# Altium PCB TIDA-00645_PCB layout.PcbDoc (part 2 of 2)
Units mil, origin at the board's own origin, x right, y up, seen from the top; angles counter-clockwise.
Board outline 3000 x 2000 mil, 2 copper layers (Top Layer, Bottom Layer), stack 62 mil thick; 97 components, 65 nets, 273 pads, 637 vias.
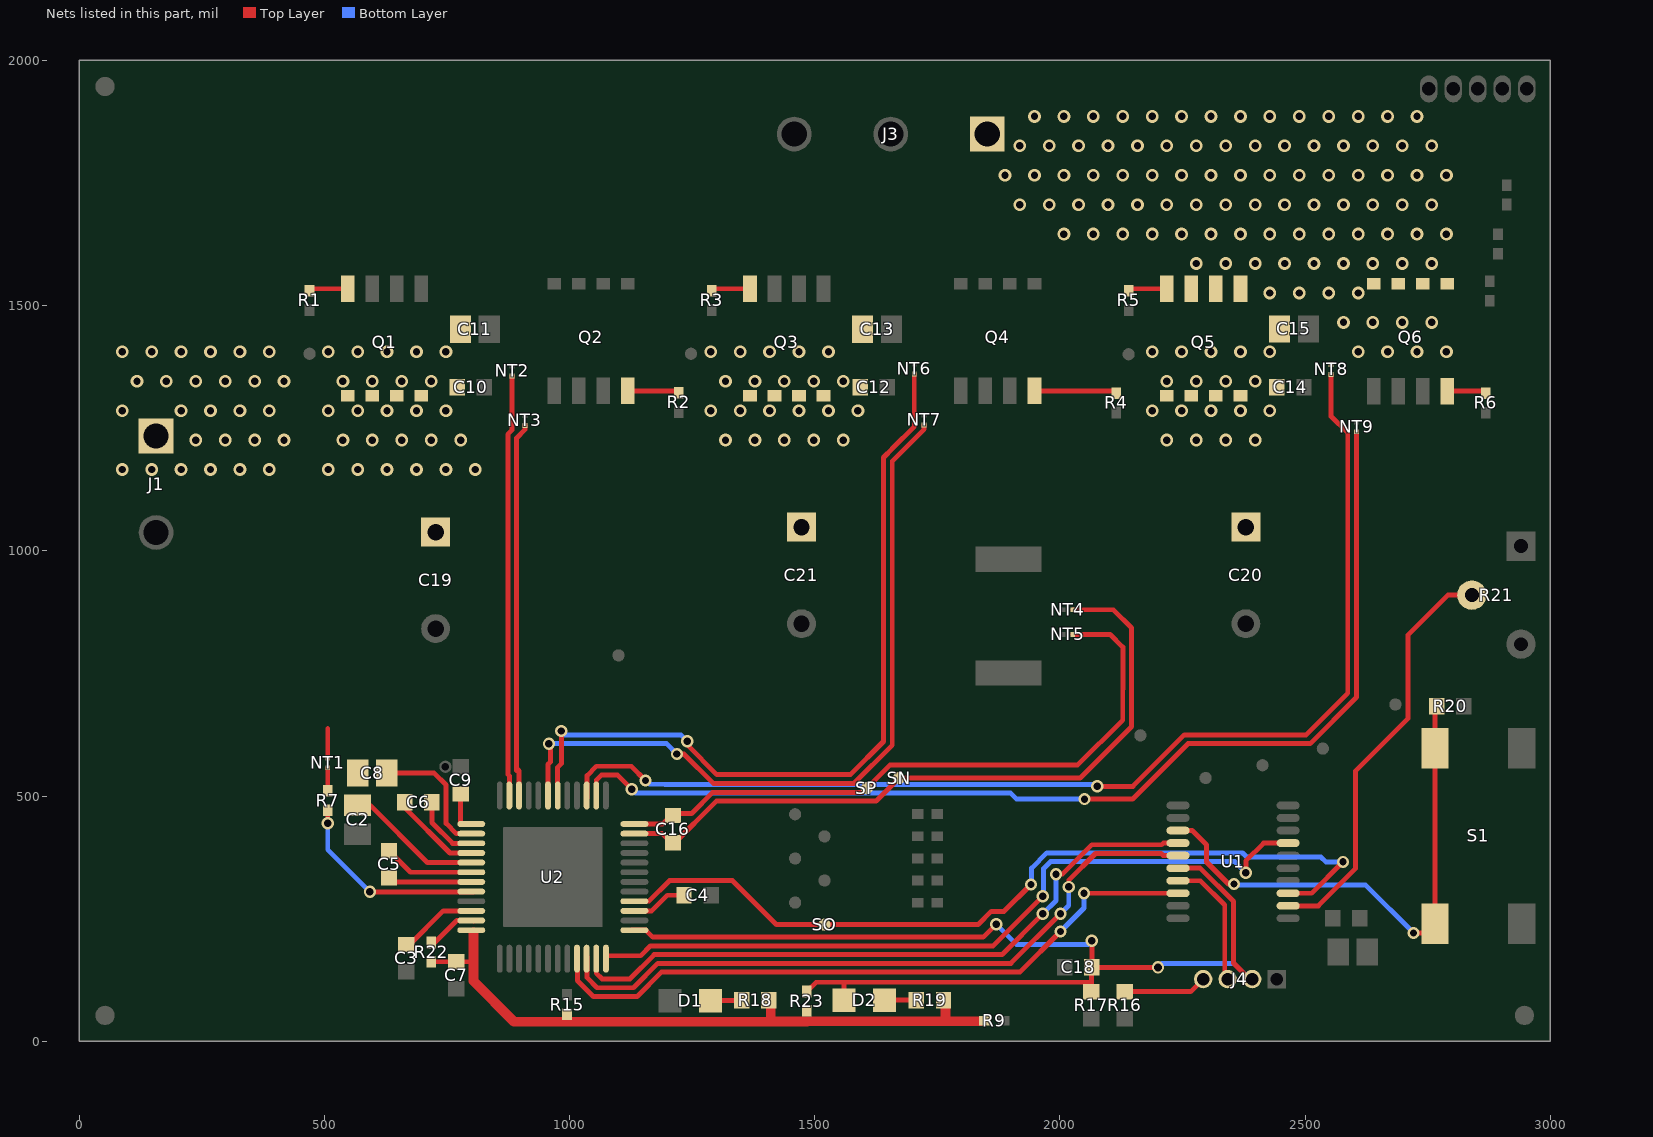
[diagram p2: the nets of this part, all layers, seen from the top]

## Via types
v1: diameter 26, hole 15, Top Layer to Bottom Layer, tented both sides, 555 vias
v2: diameter 25, hole 15, Top Layer to Bottom Layer, 56 vias
v3: diameter 19.68, hole 7.87, Top Layer to Bottom Layer, 25 vias
v4: diameter 25, hole 16, Top Layer to Bottom Layer, 1 vias

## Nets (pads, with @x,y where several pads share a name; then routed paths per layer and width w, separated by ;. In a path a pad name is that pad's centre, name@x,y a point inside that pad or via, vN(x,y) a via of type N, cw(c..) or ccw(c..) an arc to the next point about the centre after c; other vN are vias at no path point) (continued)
M_C: J3.1 NT8.2 Q5.1 Q5.2 Q5.3 Q6.5 Q6.6 Q6.7 Q6.8
  other v1: 2608,1406 2668,1406 2728,1406 2788,1406 2578,1466 2638,1466 2698,1466 2758,1466 2428,1526 2488,1526 2548,1526 2608,1526 2278,1586 2338,1586 2398,1586 2458,1586 2518,1586 2578,1586 2638,1586 2698,1586 2758,1586 2008,1646 2068,1646 2128,1646 2188,1646 2248,1646 2308,1646 2368,1646 2428,1646 2488,1646 2548,1646 2608,1646 2668,1646 2728,1646 2788,1646 1918,1706 1978,1706 2038,1706 2098,1706 2158,1706 2218,1706 2278,1706 2338,1706 2398,1706 2458,1706 2518,1706 2578,1706 2638,1706 2698,1706 2758,1706 1888,1766 1948,1766 2008,1766 2068,1766 2128,1766 2188,1766 2248,1766 2308,1766 2368,1766 2428,1766 2488,1766 2548,1766 2608,1766 2668,1766 2728,1766 2788,1766 1918,1826 1978,1826 2038,1826 2098,1826 2158,1826 2218,1826 2278,1826 2338,1826 2398,1826 2458,1826 2518,1826 2578,1826 2638,1826 2698,1826 2758,1826 1948,1886 2008,1886 2068,1886 2128,1886 2188,1886 2248,1886 2308,1886 2368,1886 2428,1886 2488,1886 2548,1886 2608,1886 2668,1886 2728,1886
NetC3_1: C3.1 U2.46 | length 167
  Top Layer w10: C3.1@667,197.56 674.01,197.56 742.56,266.1 U2.46@805.57,266.1
NetC4_1: C4.1 U2.15 | length 120.2
  Top Layer w10: U2.15@1126.43,266.1 1167.44,266.1 1199.34,298 C4.1@1233.44,298
NetC5_1: C5.1 U2.42 | length 191.7
  Top Layer w10: C5.1@632,388.56 675.72,344.84 U2.42@805.57,344.84
NetC5_2: C5.2 U2.43 | length 177
  Top Layer w10: C5.2@632,333.44 640.28,325.16 U2.43@805.57,325.16
NetC6_1: C6.1 U2.40 | length 191.1
  Top Layer w10: C6.1@664.44,488 664.44,476 756.23,384.21 U2.40@805.57,384.21
NetC6_2: C6.2 U2.39 | length 145.4
  Top Layer w10: C6.2@719.56,488 719.56,446.16 761.82,403.9 U2.39@805.57,403.9
NetC8_2: C8.2 U2.38 | length 274.9
  Top Layer w10: C8.2@627.53,547 724.12,547 748.39,522.72 748.39,444.61 769.42,423.58 U2.38@805.57,423.58
NetC9_2: C9.2 U2.37 | length 88.7
  Top Layer w10: C9.2@778,504.44 778,443.27 U2.37@805.57,443.27
NetD1_1: D1.1 R18.1 | length 59.2
  Top Layer w10: D1.1@1287.34,83 R18.1@1346.5,83
NetD2_1: D2.1 R19.1 | length 61.2
  Top Layer w10: D2.1@1642.34,84 R19.1@1703.5,84
NetJ4_4: J4.4 R16.1 | length 170.5
  Top Layer w10: R16.1@2132,101.56 2266.56,101.56 J4.4@2292,127
NetQ1_4: Q1.4 R1.2 | length 77.8
  Top Layer w10: R1.2@470,1534.62 Q1.4@547.76,1534.62
NetQ2_4: Q2.4 R2.2 | length 103.6
  Top Layer w10: Q2.4@1118.91,1326.17 R2.2@1222.55,1326.17
NetQ3_4: Q3.4 R3.2 | length 77.8
  Top Layer w10: R3.2@1290,1534.62 Q3.4@1367.76,1534.62
NetQ4_4: Q4.4 R4.2 | length 166.5
  Top Layer w10: Q4.4@1947.91,1326.17 R4.2@2114.45,1326.17
NetQ5_4: Q5.4 R5.2 | length 77.8
  Top Layer w10: R5.2@2140,1534.62 Q5.4@2217.76,1534.62
NetQ6_4: Q6.4 R6.2 | length 77.5
  Top Layer w10: Q6.4@2789.91,1326 R6.2@2867.45,1326
NetR7_1: R7.1 U2.44 | length 415.2
  Top Layer w10: v2(507,445) R7.1@507,471.32 ; v2(593,305) 593.18,304.82 654.06,304.82 654.25,305 804.23,305 804.66,304.57 U2.44@805.57,305.47
  Bottom Layer w10: v2(507,445) 507,391 v2(593,305)
POT: R21.2 U1.2 | length 853.6
  Top Layer w10: U1.2@2465.2,276.43 2526.85,276.43 2602.37,351.95 2602.37,551.1 2710,658.72 2710,829 2791,910 R21.2@2840,910
PUSH: R20.1 S1.1 S1.2 U1.13 | length 1081.6
  Top Layer w10: U1.13@2240.8,429.98 2269.73,429.98 2298.71,400.99 2298.71,365.84 2343.56,321 v2(2355,321) ; v2(2721,221) 2745.55,221 S1.1@2764.42,239.87 S1.2@2764.42,598.13 R20.1@2764.42,682.91
  Bottom Layer w10: v2(2355,321) 2357.37,318.63 2623.37,318.63 v2(2721,221)
PVDD: C2.1 C8.1 C10.1 C11.1 C12.1 C13.1 C14.1 C15.1 C19.1 C20.1 C21.1 J1.1 NT1.2 Q1.5 Q1.6 Q1.7 Q1.8 Q3.5 Q3.6 Q3.7 Q3.8 Q5.5 Q5.6 Q5.7 Q5.8 U2.41 | length 346
  Top Layer w10: NT1.2@507,578 507,638 ; C2.1@568,481.53 593.47,481.53 710.47,364.53 U2.41@805.57,364.53
  other v1: 88,1166 148,1166 208,1166 268,1166 328,1166 388,1166 508,1166 568,1166 628,1166 688,1166 748,1166 808,1166 238,1226 298,1226 358,1226 418,1226 538,1226 598,1226 658,1226 718,1226 778,1226 1318,1226 1378,1226 1438,1226 1498,1226 1558,1226 2218,1226 2278,1226 2338,1226 2398,1226 88,1286 208,1286 268,1286 328,1286 388,1286 508,1286 568,1286 628,1286 688,1286 748,1286 1288,1286 1348,1286 1408,1286 1468,1286 1528,1286 1588,1286 2188,1286 2248,1286 2308,1286 2368,1286 2428,1286 118,1346 178,1346 238,1346 298,1346 358,1346 418,1346 538,1346 598,1346 658,1346 718,1346 1318,1346 1378,1346 1438,1346 1498,1346 1558,1346 2218,1346 2278,1346 2338,1346 2398,1346 88,1406 148,1406 208,1406 268,1406 328,1406 388,1406 508,1406 568,1406 628,1406 688,1406 748,1406 1288,1406 1348,1406 1408,1406 1468,1406 1528,1406 2188,1406 2248,1406 2308,1406 2368,1406 2428,1406
RESET: C18.1 D2.2 J4.2 R17.1 R23.1 U1.16 U2.13 | length 2355
  Top Layer w10: U2.13@1126.43,226.73 1155.73,226.73 1169.84,212.63 1843.63,212.63 v2(1870,239) ; R23.1@1484,101.68 1502.81,120.5 2064.06,120.5 ; D2.2@1559.66,84 1559.66,120.16 ; R17.1@2064,101.56 2064.56,102.12 C18.1@2064.56,151 C18.1@2065,151 ; v2(2065,205) C18.1@2065,151 ; v4(2200,151) C18.1@2065,151 ; U1.16@2240.8,353.2 2286.07,353.2 2353.87,285.4 2353.87,159.78 J4.2@2386.65,127
  Bottom Layer w10: v2(1870,239) 1911.75,197.25 2057.25,197.25 v2(2065,205) ; v4(2200,151) 2207.57,158.57 2355.08,158.57 J4.2@2386.65,127
S_N: C16.1 NT4.1 SN.1 U2.23 | length 1467.8
  Top Layer w10: U2.23@1126.43,423.58 1188.92,423.58 1211,401.5 1299.35,489.85 1624.85,489.85 ; 1624.72,489.72 1624.85,489.85 ; NT4.1@2026,880 2109,880 2146.13,842.87 2146.13,672.13 ; 2146,675 2146,642 2041,537 SN.1@1672,537 1624.85,489.85
S_P: C16.2 NT5.1 SP.1 U2.24 | length 1351.5
  Top Layer w10: U2.24@1126.43,443.27 1189.77,443.27 1211,464.5 1248.71,464.5 1291.95,507.73 1597.73,507.73 SP.1@1606,516 1653.25,563.25 2035.43,563.25 2128,655 2128,718.81 ; NT5.1@2026,830 2102,830 2128.25,803.75 2128.25,718.25
SCLK: U1.7 U2.12 | length 1550.8
  Top Layer w10: U2.12@1074.27,174.57 1145.02,174.57 1165.2,194.75 1863.75,194.75 v2(1965,296) ; v2(2379,344) 2379,368 2415.39,404.39 U1.7@2465.2,404.39
  Bottom Layer w10: v2(1965,296) 1966.37,297.37 1966.37,352.1 1980.65,366.38 2356.62,366.38 v2(2379,344)
SCS: U1.18 U2.9 | length 1393.8
  Top Layer w10: U2.9@1015.21,174.57 1016.12,173.66 1016.12,124.1 1048.72,91.5 1137.78,91.5 1187.41,141.13 1918.13,141.13 v2(2001,224) ; v2(2049,302) U1.18@2240.8,302.02
  Bottom Layer w10: v2(2001,224) 2049,272 v2(2049,302)
SDI: U1.15 U2.10 | length 1404.1
  Top Layer w10: U2.10@1034.9,174.57 1035.8,173.66 1035.8,129.7 1056.13,109.37 1130.37,109.37 1180.01,159 1900,159 v2(2001,260) ; v2(2018,315) 2018,328.72 2072.36,383.09 2206,383.09 2210.29,378.8 U1.15@2240.8,378.8
  Bottom Layer w10: v2(2001,260) 2018,277 v2(2018,315)
SDO: U1.14 U2.11 | length 1373
  Top Layer w10: U2.11@1054.58,174.57 1054.58,139.15 1066.49,127.24 1122.97,127.24 1172.6,176.88 1881.88,176.88 v2(1965,260) ; v2(1992,341) 2005,341 2064.96,400.96 2207.19,400.96 2210.61,404.39 U1.14@2240.8,404.39
  Bottom Layer w10: v2(1965,260) 1992,287 v2(1992,341)
SH_A: NT2.1 U2.35 | length 862
  Top Layer w10: 874.25,544.47 874.25,1238 883,1246.75 NT2.1@883,1357 ; U2.35@877.42,495.43 877.42,541.31
SH_B: NT6.1 U2.30 | length 1646.3
  Top Layer w10: U2.30@975.84,495.43 975.84,558.84 983.37,566.37 983.37,632.63 v2@986,630 ; v2(1240,612) 1240,604.45 1300.4,544.05 1572.77,544.05 1640.13,611.4 1640.13,1190.53 1658.87,1209.28 1658.87,1209.8 1659.39,1209.8 1703,1253.4 NT6.1@1703,1361
  Bottom Layer w10: v2(983,633) 991.13,624.87 1227.13,624.87 v2(1240,612)
SH_C: NT8.1 U2.27 | length 2365.8
  Top Layer w10: U2.27@1034.9,495.43 1035.8,496.34 1035.8,542.01 1054.73,560.94 1126.06,560.94 v2(1155,532) ; v2(2076,520) 2148.72,520 2253.72,625 2502,625 2586.76,709.76 2586.76,1241.24 2553,1274 NT8.1@2553,1360
  Bottom Layer w10: v2(1155,532) 1162.75,524.25 1194.19,524.25 1194.32,524.12 2071.88,524.12 v2(2076,520)
SL_A: NT3.1 U2.34 | length 774.6
  Top Layer w10: 892.13,551.87 892.13,1230.25 909,1247.13 NT3.1@909,1256 ; 892.13,556.87 897.1,551.9 U2.34@897.1,495.43
SL_B: NT7.1 U2.31 | length 1560.8
  Top Layer w10: U2.31@956.16,495.43 956.16,564.74 961.37,569.95 961.37,603.63 v2(958,607) ; v2(1219,586) 1233.18,586 1293,526.18 1580.18,526.18 1658,604 1658,1183.13 1723,1248.13 NT7.1@1723,1257
  Bottom Layer w10: v2(958,607) 1198,607 v2(1219,586)
SL_C: NT9.1 U2.26 | length 2239.2
  Top Layer w10: U2.26@1054.58,495.43 1054.58,532.58 1064.76,542.76 1083,543 1098,543 v2(1127,514) ; v2(2050,494) 2148,494 2261,607 2510,607 2604.63,701.63 2604.63,1196.76 2605,1197.13 NT9.1@2605,1243
  Bottom Layer w10: v2(1127,514) 1134.62,506.38 1186.79,506.38 1186.92,506.25 1899.47,506.25 1911.72,494 v2(2050,494)
SO1: SO.1 U1.3 U2.16 | length 1730.5
  Top Layer w10: U2.16@1126.43,285.79 1161.85,285.79 1204.06,328 1332,328 1422,238 SO.1@1520,238 1833,238 1860,265 1886,265 v2(1941,320) ; U1.3@2465.2,302.02 2513.02,302.02 v2(2577,366)
  Bottom Layer w10: v2(1941,320) 1942.37,321.37 1942.37,353.38 1973.25,384.25 2372.31,384.25 2380.5,376.06 2532.06,376.06 2542.12,366 v2(2577,366)
TEST: J4.3 U1.17 | length 258.8
  Top Layer w10: U1.17@2242.76,327.61 2286.39,327.61 2336,278 J4.3@2336,133
VDRAIN: NT1.1 R7.2 | length 47.3
  Top Layer w10: R7.2@507,510.69 NT1.1@507,558
VREG: C7.1 R9.2 R15.2 R18.2 R19.2 R22.2 R23.2 U2.48 | length 1342.9
  Top Layer w10: R22.2@718,162.31 803.69,162.31
  Top Layer w20: U2.48@804,222.3 804,123 886.97,40.03 995.01,40.14 1410.5,40.56 1484.02,40.64 1766.5,40.92 1842.38,41 R9.2@1843,41 ; 1410.5,42.06 R18.2@1410.5,84 ; 1766.5,41.42 R19.2@1766.5,84
WAKE: R22.1 U2.47 | length 107.4
  Top Layer w10: R22.1@718,201.68 725.42,201.68 770.15,246.42 805.57,246.42 U2.47@804.66,245.51
pads on no net: FID1.1 FID2.1 FID3.1 U2.6 U2.7 U2.17 U2.18

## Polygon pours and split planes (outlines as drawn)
M_C on Top Layer "Top Layer-M_C" (solid, remove dead copper, pour order 45): 1720,2003 1723,2000 2531,2000 2637,2000 2820,1817 2820,1375 2168,1375 1724,1819 1724,1849
M_A on Top Layer "Top Layer-M_A" (solid, remove dead copper, pour order 43): -1,1463.8 -1,1880 118,1999 897,1999 1592,1999 1592,1734 1574,1716 1290,1432 1290,1301 878,1348 878,1463.8 282.03,1331.03
M_B on Top Layer "Top Layer-M_B" (solid, remove dead copper, pour order 41): 1290,1453 1290,1523 1564,1797 1564,1969 1745,1969 1744,1968 1744,1803 1745,1803 1960,1588 2044,1588 2111,1588 2137,1562 2143,1556 2143,1325 1326,1325 1304,1347
BRIDGE on Top Layer "Top Layer-BRIDGE" (solid, remove dead copper, pour order 39): 2598.23,1355 2820,1355 2820,1046 2598.23,824.23 2591.02,835.98 2598.23,977.85
BRIDGE on Top Layer "Top Layer-BRIDGE" (solid, remove dead copper, pour order 38): 1658,876 2163,876 2164,877 2164,934.72 2115,983.72 2118,986.72 2118,1356 1707,1356 1706,1355 1705,1354 1705,1255.4 1640.13,1190.53
BRIDGE on Top Layer "Top Layer-BRIDGE" (solid, remove dead copper, pour order 37): 877,1353 878,1352 1245,1352 1245,930 892,577 874.25,577
PVDD on Top Layer "Top Layer-PVDD" (solid, remove dead copper, pour order 35): 0,1473 786,1473 786,1304 790,1300 791,1301 1247,1301 1247,1444.38 1271.62,1469 1272.62,1470 1609,1470 1609,1301 1610,1300 1650,1300 2142,1300 2144,1302 2144,1468 2458,1468 2458,1300 2466,1300 2568.88,1197.12 2568.88,963.12 2568,964 1246,964 469,964 470,963 470,760 471,760 588,643 588,519 588,463 585,460 541.9,460 541.9,583.1 378,747 378,1110 342,1146 -2,1146
GND on Top Layer "Top Layer-GND" (solid, remove dead copper, pour order 44): -0.43,1780.12 -0.43,-17.5 2997.05,-17.5 3002.05,-12.5 3002.05,1780.12
M_A on Bottom Layer "Bottom Layer-M_A" (solid, remove dead copper, pour order 48): 0,1476.81 0,2000 1567,2000 1570,2003 1580,1993 1580,1686 1580,1683 1230,1333 1224,1327 455.19,1327
M_C on Bottom Layer "Bottom Layer-M_C" (solid, remove dead copper, pour order 47): 1738,2000 1738,1769 1743,1764 2059.03,1447.97 2076.01,1447.97 2366.03,1447.97 2434,1380 2821,1380 2821,1853 2752,1922 2752,1949.87 2752,2002
M_B on Bottom Layer "Bottom Layer-M_B" (solid, remove dead copper, pour order 46): 1361,1450 1361,1593 1361,1594 1564,1797 1564,2000 1744,2000 1744,1803 1745,1803 1960,1588 2111,1588 2153,1546 2153,1452 2121.13,1452 1979.21,1310.08 1946.3,1343 1699,1343
BRIDGE on Bottom Layer "Bottom Layer-BRIDGE" (solid, remove dead copper, pour order 40): 884.65,1295.24 884.65,916.6 2661.6,916.6 2820,1075 2820,1397.96
PVDD on Bottom Layer "Bottom Layer-PVDD" (solid, remove dead copper, pour order 36): 2,1145 874,1145 877.13,1148.13 877.13,1195 2454,1195 2470,1211 2470,1315.3 2470,1434 2471,1435 2471,1458 2471,1460 2455,1476 1363,1476 20,1476 0,1456
GND on Bottom Layer "Bottom Layer-GND" (solid, remove dead copper, pour order 42): -5.28,2000 2994.72,2000 2994.72,-5.57 -5.28,-5.57

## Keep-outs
Keep-Out Layer:
  lines w10: 3000,2000 0,2000 0,0 3000,0 3000,2000 ; 3000,2000 3000,2000
  text ".Layer_Name" at 577,-858.49 h60

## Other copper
Top Layer:
  rectangle net GND: 1066,339 1175,409
  rectangle net PVDD: 594,466 604,474
  rectangle net PVDD: 583,460 609,468
  rectangle net PVDD: 507,583 552,638
  rectangle net BRIDGE: 1723,1297.05 1743,1351
  rectangle net M_A: 878,1372 920,1436
  rectangle net M_B: 1698,1376.39 1738.49,1436
  rectangle net M_C: 2548,1375 2599.39,1426.15
  rectangle net BRIDGE: 1719,1293 1752,1334
  text ".Layer_Name" at 577,-858.49 h60
Bottom Layer:
  text ".Layer_Name" at 577,-858.49 h60

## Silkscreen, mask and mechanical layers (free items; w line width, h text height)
Top Overlay:
  lines w10: 1157,760 1158,761 ; 1158,864 1158,865
  text "TIDA-00645" at 390,1904 h40
  text "MOTA" at 1204,1838 h30
  text "MOTC" at 1993,1838 h30
  text "GND" at 2768,1795 h30 r90
  text "H_C" at 2817,1795 h30 r90
  text "H_B" at 2867,1795 h30 r90
  text "H_A" at 2917,1795 h30 r90
  text "DVCC" at 2969,1765 h30 r90
  text "MOTB" at 1607,1599 h30
  text "PVDD" at 108,1362 h30
  text "SPEED" at 2817,1117 h30
  text "GND" at 120,885 h30
  text "FAULTn" at 1150,140 h30
  text "PWRGD" at 1521,139 h30
  text "DIRECTION" at 2730,138 h30
  text ".Layer_Name" at 577,-858.49 h60
Bottom Overlay:
  text ".Layer_Name" at 577,-858.49 h60
Top Paste:
  text ".Layer_Name" at 577,-858.49 h60
Bottom Paste:
  text ".Layer_Name" at 577,-858.49 h60
Top Solder:
  text ".Layer_Name" at 577,-858.49 h60
  text ".Layer_Name" at 577,-858.49 h60
Bottom Solder:
  text ".Layer_Name" at 577,-858.49 h60
Drill Guide:
  text ".Layer_Name" at 577,-858.49 h60
M1 Board Outline:
  lines w10: 0,0 0,2000 3000,2000 3000,0 ; 0,0 0,0 ; 0,0 3000,0 ; 3000,0 3000,0
  text ".Layer_Name" at 577,-858.49 h60
M2 Board Dimensions:
  rectangle: 125,-400 500,-275
  rectangle: 0,-275 125,-150
  lines w7: 0,-275 1000,-275 ; 125,-400 125,-150 ; 250,-400 250,-150 ; 500,-400 500,-150 ; 750,-400 750,-150 ; 0,-400 0,-150 1000,-150 1000,-400 0,-400
  text ".Layer_Name" at 577,-858.49 h60
M3 3D STEP Top:
  text ".Layer_Name" at 577,-858.49 h60
M4 3D STEP Bottom:
  text ".Layer_Name" at 577,-858.49 h60
M5 Assembly Top:
  lines w10: -292,-930.17 6308,-930.17 ; -292,-726.83 6310,-726.83 ; -292,-523.5 -292,-1133.5 3713,-1133.5 6310,-1133.5 6310,-523.5 -291.5,-523.5 -291.5,-1133.5 1284,-1133.5 ; 2173,-1133.5 2173,-523.5 ; 3440,-726.83 3440,-523.5 ; 4280,-726.83 4280,-523.5 ; 4902,-1140 4902,-937.17
  text "COMPONENTS MARKED 'DNP' SHOULD NOT BE POPULATED." at 1153.5,-318.5 h60
  text "ASSEMBLY VARIANT:" at 1153,-434 h60
  text ".VariantName" at 2189,-434 h60
  text "PCB VIEWED FROM TOP SIDE" at -228.5,-655.67 h60
  text "BOARD #:" at 2248,-655.67 h60
  text ".PRJ_Number" at 2793.5,-655.67 h60
  text "REV:" at 3638,-655.67 h60
  text ".PCB_Rev" at 3929.5,-655.67 h60
  text "SVN REV:" at 4476,-655.67 h60
  text ".VersionControl_RevNumber" at 4982,-655.67 h60
  text "TID #:" at 2248,-859 h60
  text ".TID" at 2793.5,-859 h60
  text "PLOT NAME =" at -228.5,-1064.34 h60
  text ".plot_File_Name" at 577,-1064.34 h60
  text "GENERATED    :" at 2250,-1064.34 h60
  text ".Print_Date" at 3119.5,-1064.34 h60
  text ".Print_Time" at 3848.5,-1064.34 h60
  text "TEXAS INSTRUMENTS" at 5113,-1064.34 h60
M6 Assembly Bottom:
  lines w10: -292.5,-727.33 6309.5,-727.33 ; -290.5,-930.67 6309.5,-930.67 ; 1115.5,-1140.5 1115.5,-937.67 ; 1737.5,-727.33 1737.5,-524 ; 2577.5,-727.33 2577.5,-524 ; 3844.5,-1134 3844.5,-524 ; 4733.5,-1134 6309,-1134 6309,-524 -292.5,-524 -292.5,-1134 2304.5,-1134 6309.5,-1134 6309.5,-524
  text "COMPONENTS MARKED 'DNP' SHOULD NOT BE POPULATED." at 6102,-318 h60
  text ".VariantName" at 5058,-434 h60
  text "ASSEMBLY VARIANT:" at 6097,-434 h60
  text ".VersionControl_RevNumber" at 1035.5,-656.17 h60
  text "SVN REV:" at 1541.5,-656.17 h60
  text ".PCB_Rev" at 2088,-656.17 h60
  text "REV:" at 2379.5,-656.17 h60
  text ".PRJ_Number" at 3224,-656.17 h60
  text "BOARD #:" at 3769.5,-656.17 h60
  text "PCB VIEWED FROM BOTTOM SIDE" at 6246,-656.17 h60
  text ".PRJ_Number" at 3224,-859.5 h60
  text "TID #:" at 3769.5,-859.5 h60
  text "TEXAS INSTRUMENTS" at 904.5,-1064.84 h60
  text ".Print_Time" at 2169,-1064.84 h60
  text ".Print_Date" at 2898,-1064.84 h60
  text "GENERATED    :" at 3767.5,-1064.84 h60
  text ".plot_File_Name" at 5440.5,-1064.84 h60
  text "PLOT NAME =" at 6246,-1064.84 h60
M9 Title Sheet:
  drawing of 57 lines, arcs and shapes, not listed
  text "1" at 739.84,8036.5 h70
  text "2" at 3235.5,8036.5 h70
  text "3" at 5724.84,8036.5 h70
  text "4" at 8231.51,8036.5 h70
  text "5" at 10730.5,8036.5 h70
  text "6" at 13235.5,8036.5 h70
  text "A" at -416.5,6893.5 h70
  text "A" at 14383.5,6893.5 h70
  text "B" at -416.5,4513.5 h70
  text "B" at 14383.5,4513.5 h70
  text "C" at -416.5,2138.5 h70
  text "C" at 14383.5,2138.5 h70
  text "PROJECT TITLE:" at 11343.5,277.5 h45
  text ".PRJ_Title" at 11393.5,144.17 h70
  text "DESIGNED FOR:" at 11343.5,-23.5 h45
  text ".PRJ_Customer" at 11393.5,-163.5 h70
  text "D" at -416.5,-231.5 h70
  text "D" at 14383.5,-231.5 h70
  text "FILE NAME:" at 11343.5,-323.5 h45
  text ".PCB_File_Name_No_Path" at 11393.5,-443.5 h70
  text "Texas Instruments (TI) and/or its licensors do not warrant the accuracy or completeness of this specification" at 6374,-605.34 h45
  text "ENGINEER:" at 11343.5,-613.5 h45
  text "LAYOUT BY:" at 12848.5,-613.5 h45
  text "or any information contained therein. TI and/or its licensors do not warrant that this design will meet" at 6329.01,-718 h45
  text ".PRJ_Engineer" at 11393.5,-768.49 h70
  text ".PCB_Layout" at 12899,-768.49 h70
  text "the specifications, will be suitable for your application or fit for any particular purpose, or will operate in" at 6329.01,-830.67 h45
  text ".Layer_Name" at 577,-858.49 h60
  text "ALTIUM DESIGNER VERSION:" at 12848.5,-923.5 h45
  text "an implementation. TI and/or its licensors do not warrant that the design is production worthy. You should" at 6329.01,-943.33 h45
  text "completely validate and test your design implementation to confirm the system functionality for your application." at 6374,-1056 h45
  text ".print_Scale" at 11393.5,-1056.83 h70
  text ".Application_BuildNumber" at 12899,-1056.83 h70
  text "1" at 739.84,-1263.5 h70
  text "2" at 3235.5,-1263.5 h70
  text "3" at 5724.84,-1263.5 h70
  text "4" at 8231.51,-1263.5 h70
  text "5" at 10730.5,-1263.5 h70
  text "6" at 13235.5,-1263.5 h70
M10 Fab Notes:
  drawing of 185 lines, arcs and shapes, not listed
  text "DESIGN INFORMATION" at 12381.02,5910 h60
  text "MIN. TRACK WIDTH:" at 11736.46,5730 h60
  text "8" at 12832.7,5730 h60
  text "MIL" at 12987.46,5730 h60
  text "MIN. CLEARANCE:" at 11736.46,5598 h60
  text "0.2" at 12772.7,5598 h60
  text "mm" at 12987.46,5598 h60
  text "MIN. VIA PAD SIZE:" at 11736.46,5466 h60
  text "24" at 12802.71,5466 h60
  text "MIL" at 12987.46,5466 h60
  text "0.05mm (2MIL)" at 12431.46,5324.29 h60
  text "MINIMUM ANNULAR RING" at 11407.23,5320 h60
  text "EXTERNAL" at 13139.46,5320 h60
  text "PER" at 11607.23,5202 h60
  text "IPC-D-275 CLASS 2 LEVEL C" at 11827.23,5202 h60
  text "MIL, HOLES" at 13315.46,5089.71 h60
  text "+/-" at 12923,5089 h60
  text "+/-" at 13777,5089 h60
  text "REGISTRATION TOLERANCES:" at 11407.23,5084 h60
  text "METAL" at 12607,5084 h60
  text "5" at 13183.2,5084 h60
  text "3" at 14016.2,5084 h60
  text "MIL" at 14132.46,5084 h60
  text "MATERIAL:" at 11332.46,4874.54 h60
  text "FR-4 High Tg" at 12318.9,4734.21 h60
  text "FR-408" at 11753.46,4725.64 h60
  text "X" at 12165.46,4725.64 h60
  text "OTHER" at 13241.46,4725.64 h60
  text "62 MIL (1.6mm) +/-10%" at 12073.56,4562.92 h60
  text "THICKNESS:" at 11407.23,4558.64 h60
  text "X" at 11945.4,4558.64 h60
  text "OTHER" at 13358.46,4558.64 h60
  text "TOLERANCE:" at 11407.23,4400.64 h60
  text "X" at 12246.53,4400.64 h60
  text "ANSI IPC-6012 TYPE 3 CLASS 2" at 12433.48,4400.64 h60
  text "OTHER +/-" at 12433.46,4244.64 h60
  text "BOW & TWIST:" at 11407.23,4087.64 h60
  text "X" at 12246.53,4087.64 h60
  text "ANSI IPC-6012 TYPE 3 CLASS 2" at 12433.48,4087.64 h60
  text "OTHER +/-" at 12433.46,3929.13 h60
  text "DRILLING:" at 11332.46,3790.64 h60
  text "REFERENCE:" at 11407.23,3673.64 h60
  text "X" at 12055.46,3673.64 h60
  text "AS SHOWN" at 12242.46,3673.64 h60
  text "X" at 12956.46,3673.64 h60
  text "NC_DRILL FILES" at 13093.46,3673.64 h60
  text "PTH MIN COPPER THICKNESS:" at 11407.23,3515.64 h60
  text "X" at 12757.46,3515.64 h60
  text "1MIL" at 12894.46,3515.64 h60
  text "OTHER" at 13391.46,3515.64 h60
  text "BOARD FINISH:" at 11332.46,3356.64 h60
  text "SILKSCREEN:" at 11487.68,3238.64 h60
  text "X" at 12436.46,3238.64 h60
  text "TOP" at 12562.46,3238.64 h60
  text "X" at 12946.46,3238.64 h60
  text "BOTTOM" at 13073.46,3238.64 h60
  text "SILKSCREEN COLOR:" at 11487.68,3071.64 h60
  text "X" at 12435.42,3071.64 h60
  text "WHITE" at 12562.46,3071.64 h60
  text "OTHER" at 13073.46,3071.64 h60
  text "SOLDER RESIST COLOR:" at 11487.68,2901.64 h60
  text "X" at 12055.42,2742.44 h60
  text "GREEN" at 12182.46,2742.44 h60
  text "BLUE" at 12773.46,2742.44 h60
  text "OTHER" at 13311.46,2742.44 h60
  text "IMMERSION GOLD (ENIG)" at 12393.46,2553.92 h60
  text "ENEPIG" at 13731,2550.64 h60
  text "SURFACE FINISH:" at 11332.46,2549.64 h60
  text "X" at 12206.51,2549.64 h60
  text "IMM. TIN/SILVER OR EQUIV" at 11662,2392.64 h60
  text "OTHER" at 13093.46,2392.64 h60
  text "ARRAY/PANEL:" at 11332.46,2213.64 h60
  text "CUT AND TRIM PER MECH LAYER 1" at 12393.46,2209.35 h60
  text "N.C. ROUTE" at 12393.46,2057.64 h60
  text "X" at 13072.46,2057.64 h60
  text "V. SCORE" at 13259.46,2057.64 h60
  text "CERTIFICATION:" at 11332.46,1920.64 h60
  text "MATERIALS AND WORKMANSHIP FOR ALL PCBS" at 12057.46,1920.64 h60
  text "TO MEET OR EXCEED THE REQUIREMENTS OF:" at 12057.46,1822.64 h60
  text "X" at 11683.96,1686.13 h60
  text "ANSI IPC-A-600F CLASS ->" at 11822.96,1686.13 h60
  text "X" at 13462.02,1686.13 h60
  text "2" at 13580.96,1686.14 h60
  text "1" at 13265.96,1684.64 h60
  text "3" at 13934.96,1684.64 h60
  text "X" at 11686.02,1526.64 h60
  text "UL 94V-0" at 11822.96,1526.64 h60
  text "X" at 12498.02,1526.64 h60
  text "RoHS" at 12634.96,1526.64 h60
  text "OTHER" at 13279.36,1526.64 h60
  text "PER ORDER" at 13676.42,1526.64 h60
  text "ADDITIONAL REQUIREMENTS:" at 11332.46,1385.64 h60
  text "MICROSECTION:" at 11407.23,1270.64 h60
  text "YES" at 12312.96,1270.64 h60
  text "REQUIRED" at 13174.46,1114.49 h60
  text "BARE BOARD ELEC. TEST:" at 11407.23,1111.64 h60
  text "NONE" at 12712.96,1111.64 h60
  text "X" at 13047.46,1111.64 h60
  text "PER ORDER" at 13766.46,1111.64 h60
  text "MANUFACTURER'S UL:" at 11407.23,954.64 h60
  text "RAIL" at 12572.96,950.35 h60
  text "METAL" at 13064.77,950.35 h60
  text "X" at 13440,950 h60
  text "SILK" at 13576.46,950.35 h60
  text ".Layer_Name" at 577,-858.49 h60
M11 Gerber Information:
  lines w10: -292,-930.17 6308,-930.17 ; -292,-726.83 6310,-726.83 ; -292,-523.5 -292,-1133.5 3713,-1133.5 6310,-1133.5 6310,-523.5 -291.5,-523.5 -291.5,-1133.5 1284,-1133.5 ; 2173,-1133.5 2173,-523.5 ; 3440,-726.83 3440,-523.5 ; 4280,-726.83 4280,-523.5 ; 4902,-1140 4902,-937.17
  text "ALL ARTWORK VIEWED FROM TOP SIDE" at -228.5,-655.67 h60
  text "BOARD #:" at 2248,-655.67 h60
  text ".PRJ_Number" at 2793.5,-655.67 h60
  text "REV:" at 3638,-655.67 h60
  text ".PCB_Rev" at 3929.5,-655.67 h60
  text "SVN REV:" at 4476,-655.67 h60
  text ".VersionControl_RevNumber" at 4982,-655.67 h60
  text "LAYER NAME =" at -228.5,-858.49 h60
  text "TID #:" at 2248,-859 h60
  text ".TID" at 2793.5,-859 h60
  text "PLOT NAME =" at -228.5,-1064.34 h60
  text ".plot_File_Name" at 577,-1064.34 h60
  text "GENERATED    :" at 2250,-1064.34 h60
  text ".Print_Date" at 3119.5,-1064.34 h60
  text ".Print_Time" at 3848.5,-1064.34 h60
  text "TEXAS INSTRUMENTS" at 5113,-1064.34 h60
M12 Stackup:
  drawing of 191 lines, arcs and shapes, not listed
  text "Layer" at 9790.34,7830 h60
  text "Name" at 10200.26,7830 h60
  text "Material" at 11130,7830 h60
  text "Thickness" at 11989.77,7830 h60
  text "Constant" at 12639.6,7830 h60
  text "Board Layer Stack" at 13209.46,7830 h60
  text "1" at 9790.34,7710 h60
  text "Top Overlay" at 10200.26,7710 h60
  text "2" at 9790.34,7590 h60
  text "Top Solder" at 10200.26,7590 h60
  text "Solder Resist" at 11130,7590 h60
  text "0.40mil" at 11989.77,7590 h60
  text "3.5" at 12639.6,7590 h60
  text "3" at 9790.34,7470 h60
  text "Top Layer" at 10200.26,7470 h60
  text "Copper" at 11130,7470 h60
  text "1.40mil" at 11989.77,7470 h60
  text "4" at 9790.34,7350 h60
  text "Dielectric1" at 10200.26,7350 h60
  text "FR-4" at 11130,7350 h60
  text "59.20mil" at 11989.77,7350 h60
  text "4.8" at 12639.6,7350 h60
  text "5" at 9790.34,7230 h60
  text "Bottom Layer" at 10200.26,7230 h60
  text "Copper" at 11130,7230 h60
  text "1.40mil" at 11989.77,7230 h60
  text "6" at 9790.34,7110 h60
  text "Bottom Solder" at 10200.26,7110 h60
  text "Solder Resist" at 11130,7110 h60
  text "0.40mil" at 11989.77,7110 h60
  text "3.5" at 12639.6,7110 h60
  text "7" at 9790.34,6990 h60
  text "Bottom Overlay" at 10200.26,6990 h60
  text ".Layer_Name" at 577,-858.49 h60
M13 Component Bodies Top:
  text ".Layer_Name" at 577,-858.49 h60
M14 Component Bodies Bottom:
  text ".Layer_Name" at 577,-858.49 h60
M15 Courtyards Top:
  text ".Layer_Name" at 577,-858.49 h60
M16 Courtyards Bottom:
  text ".Layer_Name" at 577,-858.49 h60
Drill Drawing:
  circle w1: c5677.9,3258.91 r20.77
  circle w1: c5677.9,3134.29 r12.46
  circle w1: c5677.9,3134.29 r20.77
  lines w1: 5657.13,2365.79 5657.13,2376.17 5667.51,2386.56 5657.13,2396.94 5657.13,2407.33 5667.51,2407.33 5677.9,2396.94 5688.28,2407.33 5698.67,2407.33 5698.67,2396.94 5688.28,2386.56 5698.67,2376.17 5698.67,2365.79 5688.28,2365.79 5677.9,2376.17 5667.51,2365.79 5657.13,2365.79 ; 5657.13,2500.79 5667.51,2500.79 5667.51,2490.41 5688.28,2490.41 5688.28,2500.79 5698.67,2500.79 5698.67,2521.56 5688.28,2521.56 5688.28,2531.95 5667.51,2531.95 5667.51,2521.56 5657.13,2521.56 5657.13,2500.79 ; 5657.13,2615.03 5677.9,2625.42 5698.67,2615.03 5688.28,2635.8 5698.67,2656.57 5677.9,2646.19 5657.13,2656.57 5667.51,2635.8 5657.13,2615.03 ; 5657.13,2750.04 5667.51,2750.04 5677.9,2739.65 5688.28,2750.04 5698.67,2750.04 5688.28,2760.42 5698.67,2770.81 5688.28,2770.81 5677.9,2781.19 5667.51,2770.81 5657.13,2770.81 5667.51,2760.42 5657.13,2750.04 ; 5657.13,2905.82 5698.67,2905.82 5677.9,2864.27 5657.13,2905.82 ; 5657.13,2988.9 5698.67,2988.9 5698.67,3030.44 5657.13,3030.44 5657.13,2988.9
  lines w12: 5600,2328.4 7629.11,2328.4 ; 5600,3325.38 7629.11,3325.38 ; 5948.13,2203.78 5948.13,3450 ; 6290.32,2203.78 6290.32,3450 ; 6937.06,2203.78 6937.06,3450 ; 7206.38,2203.78 7206.38,3450 ; 5600,2203.78 7629.11,2203.78 7629.11,3450 5600,3450 5600,2203.78
  text "Symbol" at 5674.77,3362.76 h72
  text "Quantity" at 5985.52,3362.76 h72
  text "Finished Hole Size" at 6327.7,3362.76 h72
  text "Plated" at 6974.45,3362.76 h72
  text "Hole Type" at 7243.77,3362.76 h72
  text "25" at 5985.52,3238.14 h60
  text "7.87mil (0.200mm)" at 6327.7,3238.14 h60
  text "PTH" at 6974.45,3238.14 h60
  text "Round" at 7243.77,3238.14 h60
  text "612" at 5985.52,3113.52 h60
  text "15.00mil (0.381mm)" at 6327.7,3113.52 h60
  text "PTH" at 6974.45,3113.52 h60
  text "Round" at 7243.77,3113.52 h60
  text "1" at 5985.52,2988.9 h60
  text "16.00mil (0.406mm)" at 6327.7,2988.9 h60
  text "PTH" at 6974.45,2988.9 h60
  text "Round" at 7243.77,2988.9 h60
  text "4" at 5985.52,2864.27 h60
  text "25.59mil (0.650mm)" at 6327.7,2864.27 h60
  text "PTH" at 6974.45,2864.27 h60
  text "Round" at 7243.77,2864.27 h60
  text "5" at 5985.52,2739.65 h60
  text "27.56mil (0.700mm)" at 6327.7,2739.65 h60
  text "PTH" at 6974.45,2739.65 h60
  text "Round" at 7243.77,2739.65 h60
  text "3" at 5985.52,2615.03 h60
  text "28.00mil (0.711mm)" at 6327.7,2615.03 h60
  text "PTH" at 6974.45,2615.03 h60
  text "Round" at 7243.77,2615.03 h60
  text "6" at 5985.52,2490.41 h60
  text "33.46mil (0.850mm)" at 6327.7,2490.41 h60
  text "PTH" at 6974.45,2490.41 h60
  text "Round" at 7243.77,2490.41 h60
  text "5" at 5985.52,2365.79 h60
  text "51.18mil (1.300mm)" at 6327.7,2365.79 h60
  text "PTH" at 6974.45,2365.79 h60
  text "Round" at 7243.77,2365.79 h60
  text "661 Total" at 5985.52,2241.16 h60
  text ".Layer_Name" at 577,-858.49 h60

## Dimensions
0,0 to 3000,-150 on M2 Board Dimensions
0,0 to -40,2000 on M2 Board Dimensions
0,-400 to 1000,-400 on M2 Board Dimensions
